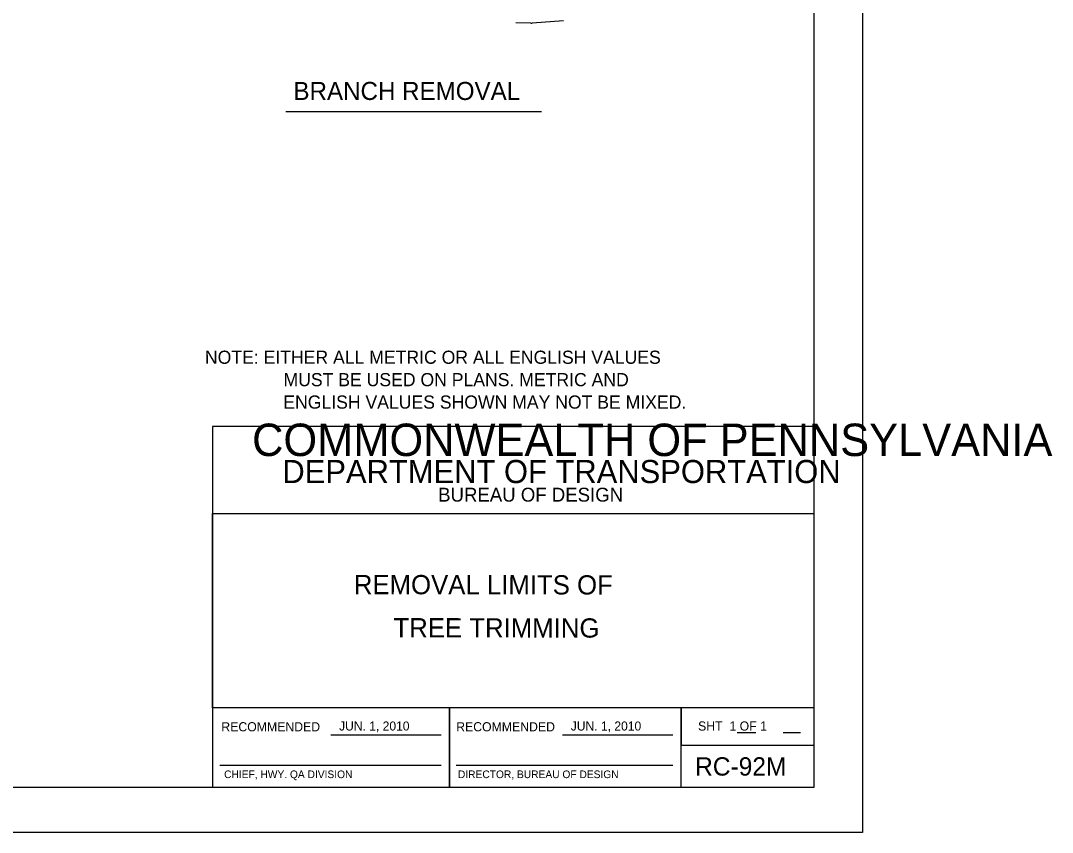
# Model space of a CAD drawing. Extents: x 639115 to 640019, y 298285 to 298879.
# Drawn here: x 639676.3 to 640019.2, y 298285.2 to 298555.2 of the extents above; entities that cross this region are included whole.
import ezdxf

# ---------------------------------------------------------------- set-up
doc = ezdxf.new("R2010")
doc.units = 0
doc.layers.add('1', color=7, linetype='Continuous')
doc.layers.add('PLT-BNDY', color=7, linetype='Continuous')

msp = doc.modelspace()

# ---------------------------------------------------------------- linework, layer by layer
at = {"layer": '1'}
for p, q in [((639845.83, 298554.34), (639840.88, 298554.48)), ((639856.64, 298555.09), (639846.24, 298554.35)), ((639764.44, 298524.97), (639849.39, 298524.97)), ((639779.35, 298317.61), (639816.04, 298317.61)), ((639856.35, 298317.61), (639893.04, 298317.61)), ((639914.45, 298318.41), (639920.6, 298318.41)), ((639929.71, 298318.41), (639935.45, 298318.41)), ((639742.43, 298307.53), (639816.04, 298307.53)), ((639820.96, 298307.53), (639893.04, 298307.53))]:
    msp.add_line(p, q, dxfattribs=at)
msp.add_lwpolyline([(639940.03, 298300.23), (639940.03, 298864.23), (639154.03, 298864.23), (639154.03, 298300.23), (639940.03, 298300.23), (639940.03, 298326.59), (639740.03, 298326.59), (639740.03, 298391.26), (639940.03, 298391.26), (639940.03, 298420.23), (639740.03, 298420.23), (639740.03, 298300.23), (639818.83, 298300.23), (639818.83, 298326.59), (639818.83, 298300.23), (639895.83, 298300.23), (639895.83, 298326.59), (639895.83, 298314.27), (639940.03, 298314.27)], dxfattribs=at)
msp.add_arc((639845.95, 298558.34), 4, 268.3153, 274.0856, dxfattribs=at)
at = {"layer": 'PLT-BNDY'}
msp.add_lwpolyline([(639115.03, 298879.23), (639956.03, 298879.23), (639956.03, 298285.23), (639115.03, 298285.23)], close=True, dxfattribs=at)

# ---------------------------------------------------------------- texts
at = {"layer": '1'}
for s, height, p in [('BRANCH REMOVAL', 6, (639766.93, 298528.78)), ('NOTE: EITHER ALL METRIC OR ALL ENGLISH VALUES', 4.375, (639737.51, 298441.04)), ('MUST BE USED ON PLANS. METRIC AND', 4.375, (639763.63, 298433.59)), ('ENGLISH VALUES SHOWN MAY NOT BE MIXED.', 4.375, (639763.56, 298426.13)), ('COMMONWEALTH OF PENNSYLVANIA', 10.7834, (639753.18, 298410.37)), ('DEPARTMENT OF TRANSPORTATION', 7.6843, (639763.25, 298401.38)), ('BUREAU OF DESIGN', 4.6221, (639815.02, 298395.21)), ('RECOMMENDED', 3.048, (639742.96, 298318.82)), ('JUN. 1, 2010', 3, (639782.09, 298319.1)), ('RECOMMENDED', 3.048, (639821.01, 298318.82)), ('JUN. 1, 2010', 3, (639859.09, 298319.1)), ('SHT  1 OF 1', 3.048, (639901.41, 298319.07)), ('RC-92M', 6.096, (639900.42, 298304.11)), ('CHIEF, HWY. QA DIVISION', 2.54, (639743.88, 298303.27)), ('DIRECTOR, BUREAU OF DESIGN', 2.54, (639821.6, 298303.27))]:
    msp.add_text(s, height=height, dxfattribs=at).set_placement(p)
for s, p in [('REMOVAL LIMITS OF', (639786.99, 298364.44)), ('TREE TRIMMING', (639800.17, 298350.09))]:
    msp.add_text(s, height=6.4, rotation=359.9181, dxfattribs=at).set_placement(p)

doc.saveas('drawing.dxf')
